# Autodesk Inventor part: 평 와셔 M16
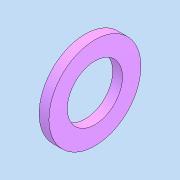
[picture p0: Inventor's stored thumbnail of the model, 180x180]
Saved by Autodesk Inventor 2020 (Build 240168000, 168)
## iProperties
Created: 2025-01
Part Number: 평 와셔 M16
Material: 강철, 연강
Description: 평면 와셔
Document SubType Name: Modeling
Designer: 1강의실14
Density: 7.85 g/cm^3
Appearance: 기본값
Author: jhkim
Sending System: Autodesk Inventor 2025
Preprocessor: ST-DEVELOPER v20
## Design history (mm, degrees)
feature "Solid1"
node "솔리드1"
